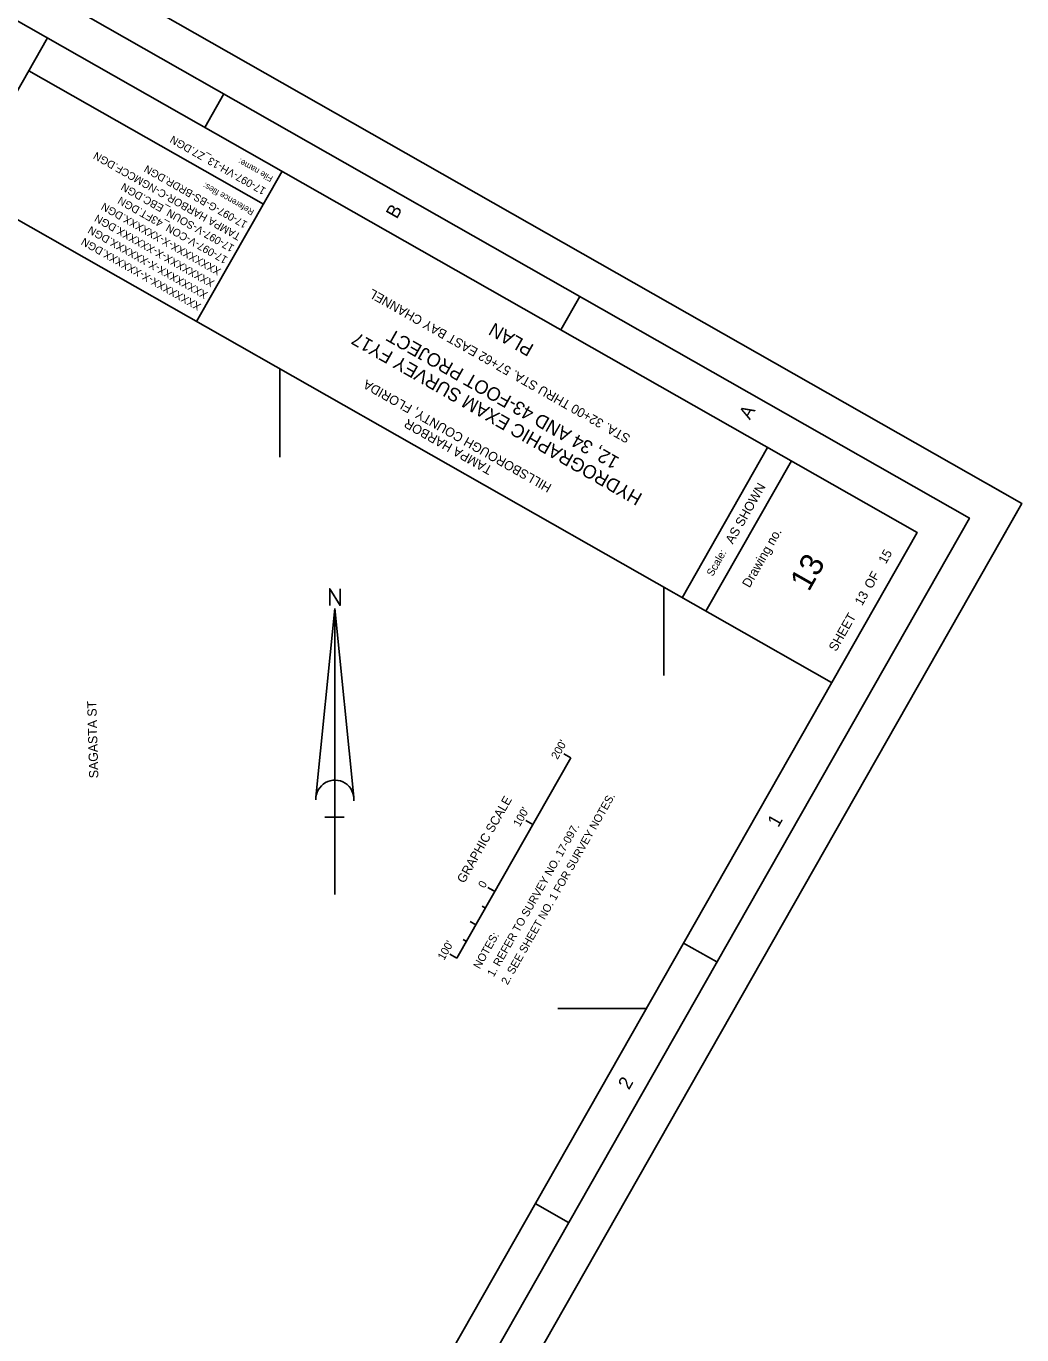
# Model space of a CAD drawing. Extents: x 517335 to 522466, y 1300833 to 1306339.
# Drawn here: x 521170 to 522466, y 1303575 to 1305279 of the extents above; entities that cross this region are included whole.
import ezdxf

# ---------------------------------------------------------------- set-up
doc = ezdxf.new("R2010")
doc.units = 0
for name, color, linetype in [('G-ANNO-NPLT', 7, 'Continuous'), ('G-ANNO-TEXT-DRWG', 7, 'Continuous'), ('G-ANNO-TEXT-PROJ', 7, 'Continuous'), ('G-ANNO-TEXT-TTLB', 7, 'Continuous'), ('G-ANNO-TTLB', 7, 'Continuous'), ('V-ANNO-NOTE', 7, 'Continuous'), ('V-ANNO-SYMB', 7, 'Continuous'), ('V-ROAD-IDEN', 7, 'Continuous'), ('V-TOPO-COOR-STAT', 7, 'Continuous')]:
    doc.layers.add(name, color=color, linetype=linetype)

msp = doc.modelspace()

# ---------------------------------------------------------------- linework, layer by layer
at = {"layer": 'G-ANNO-NPLT'}
msp.add_lwpolyline([(517335, 1302514.1), (519510.6, 1306338.6), (522465.8, 1304657.4), (520290.3, 1300833)], close=True, dxfattribs=at)
msp.add_lwpolyline([(522422.5, 1304682.3), (522465.9, 1304657.6), (522441.2, 1304614.1)], dxfattribs=at)
at = {"layer": 'G-ANNO-TTLB'}
for p, q in [((519436.8, 1306006.6), (522218.2, 1304424.4)), ((521085.8, 1305067.2), (521197.6, 1305263.8)), ((521173.3, 1305221), (521478.7, 1305047.2)), ((521427.1, 1305190.8), (521402.4, 1305147.3)), ((521391.8, 1304894.5), (521503.1, 1305090.1)), ((521890.7, 1304927.1), (521865.9, 1304883.7)), ((522023.7, 1304535), (522135, 1304730.6)), ((522054.7, 1304517.4), (522166, 1304713)), ((522068.9, 1304060.7), (522025.4, 1304085.4)), ((521876, 1303721.7), (521832.6, 1303746.4))]:
    msp.add_line(p, q, dxfattribs=at)
for points in [[(520271.6, 1300901.1), (522397.7, 1304638.7), (519529.3, 1306270.4), (517403.2, 1302532.8)], [(519548, 1306202.2), (517508.5, 1302616.7), (520289.9, 1301034.5), (522329.5, 1304620)]]:
    msp.add_lwpolyline(points, close=True, dxfattribs=at)
at = {"layer": 'V-ANNO-NOTE'}
for p, q in [((521730.5, 1304065.7), (521878.8, 1304326.5)), ((521878.8, 1304326.5), (521869.8, 1304331.6)), ((521829.4, 1304239.5), (521820.3, 1304244.7)), ((521779.9, 1304152.6), (521770.9, 1304157.8)), ((521779.9, 1304152.6), (521770.9, 1304157.8)), ((521779.9, 1304152.6), (521775.6, 1304155.1)), ((521767.6, 1304130.9), (521763.4, 1304133.3)), ((521755.2, 1304109.2), (521747.8, 1304113.4)), ((521742.9, 1304087.4), (521738.7, 1304089.8)), ((521730.5, 1304065.7), (521721.4, 1304070.9))]:
    msp.add_line(p, q, dxfattribs=at)
at = {"layer": 'V-ANNO-SYMB'}
for p, q in [((521547.1, 1304275.2), (521571.8, 1304521)), ((521571.8, 1304148.6), (521571.8, 1304521)), ((521596.5, 1304275.2), (521571.8, 1304521)), ((521583.6, 1304249.2), (521558.8, 1304249.2))]:
    msp.add_line(p, q, dxfattribs=at)
msp.add_lwpolyline([(521565, 1304524.9), (521565, 1304546.7), (521578.5, 1304524.9), (521578.5, 1304546.7)], dxfattribs=at)
msp.add_arc((521571.8, 1304272.7), 24.8, 355.2984, 182.0673, dxfattribs=at)
at = {"layer": 'V-TOPO-COOR-STAT'}
for p, q in [((521500, 1304717.9), (521500, 1304832.9)), ((522000, 1304433.5), (522000, 1304548.5)), ((521976.8, 1304000), (521861.8, 1304000))]:
    msp.add_line(p, q, dxfattribs=at)

# ---------------------------------------------------------------- texts
at = {"layer": 'G-ANNO-TEXT-DRWG'}
for s, height, rotation, p in [('17-097-VH-13_Z7.DGN', 10, 150.3667, (521482.9, 1305067.5)), ('TAMPA HARBOR-C-NGMCCF.DGN', 10, 150.3667, (521450.3, 1305008.2)), ('17-097-V-SOUN_EBC.DGN', 10, 150.3667, (521441.7, 1304993)), ('XXXXXXXX-X-XXXXXX.DGN', 10, 150.3667, (521424.4, 1304962.6)), ('17-097-V-CON_43FT.DGN', 10, 150.3667, (521433, 1304977.8)), ('XXXXXXXX-X-XXXXXX.DGN', 10, 150.3667, (521415.7, 1304947.3)), ('XXXXXXXX-X-XXXXXX.DGN', 10, 150.3667, (521407.1, 1304932.1)), ('XXXXXXXX-X-XXXXXX.DGN', 10, 150.3667, (521398.4, 1304916.9)), ('STA. 32+00 THRU STA. 57+62 EAST BAY CHANNEL', 12, 150.3667, (521957.6, 1304745.7)), ('PLAN', 17.5, 150.3667, (521832, 1304863.4)), (' 13          15', 12, 60.3667, (522255.8, 1304519.8)), ('13', 30, 60.3667, (522188.6, 1304541.8))]:
    msp.add_text(s, height=height, rotation=rotation, dxfattribs=at).set_placement(p)
at = {"layer": 'G-ANNO-TEXT-PROJ'}
for s, height, p in [('17-097-G-BS-BRDR.DGN', 9.8, (521458.7, 1305023.7)), ('HYDROGRAPHIC EXAM SURVEY FY17', 17.5, (521973.3, 1304669.3)), ('12, 34 AND 43-FOOT PROJECT', 17.5, (521943.3, 1304716.5)), ('HILLSBOROUGH COUNTY, FLORIDA', 12, (521854.9, 1304681.7)), ('TAMPA HARBOR', 12, (521777.9, 1304704.8))]:
    msp.add_text(s, height=height, rotation=150.3667, dxfattribs=at).set_placement(p)
at = {"layer": 'G-ANNO-TEXT-TTLB'}
for s, height, rotation, p in [('File name:', 8, 150.3667, (521491.9, 1305082.7)), ('Reference files:', 8, 150.3667, (521467.4, 1305039.2)), ('AS SHOWN', 12, 60.3667, (522089.7, 1304603.9)), ('Drawing no.', 12, 60.3667, (522111.5, 1304547)), ('Scale:', 10, 60.3667, (522063.6, 1304561.9)), ('SHEET         OF', 12, 60.3667, (522224.2, 1304464.1))]:
    msp.add_text(s, height=height, rotation=rotation, dxfattribs=at).set_placement(p)
at = {"layer": 'G-ANNO-TTLB'}
for s, p in [('B', (521652.3, 1305027.1)), ('A', (522111.9, 1304765.7)), ('1', (522148.9, 1304235)), ('2', (521954.5, 1303893.3))]:
    msp.add_text(s, height=17.5, rotation=60.3667, dxfattribs=at).set_placement(p)
at = {"layer": 'V-ANNO-NOTE'}
for s, height, p in [("200'", 10.42, (521861.5, 1304323.6)), ('GRAPHIC SCALE', 11.666, (521740.1, 1304162.4)), ('2. SEE SHEET NO. 1 FOR SURVEY NOTES.', 10.416, (521796.5, 1304030.2)), ("100'", 10.42, (521812.2, 1304235.9)), ('1. REFER TO SURVEY NO. 17-097.', 10.416, (521778.4, 1304040.5)), ('0', 10.4, (521766.5, 1304156)), ("100'", 10.42, (521713.8, 1304062.2)), ('NOTES:', 10.42, (521760.3, 1304050.8))]:
    msp.add_text(s, height=height, rotation=60.3667, dxfattribs=at).set_placement(p)
at = {"layer": 'V-ROAD-IDEN'}
msp.add_text('SAGASTA ST', height=12, rotation=91.5397, dxfattribs=at).set_placement((521263.9, 1304300.1))

doc.saveas('drawing.dxf')
